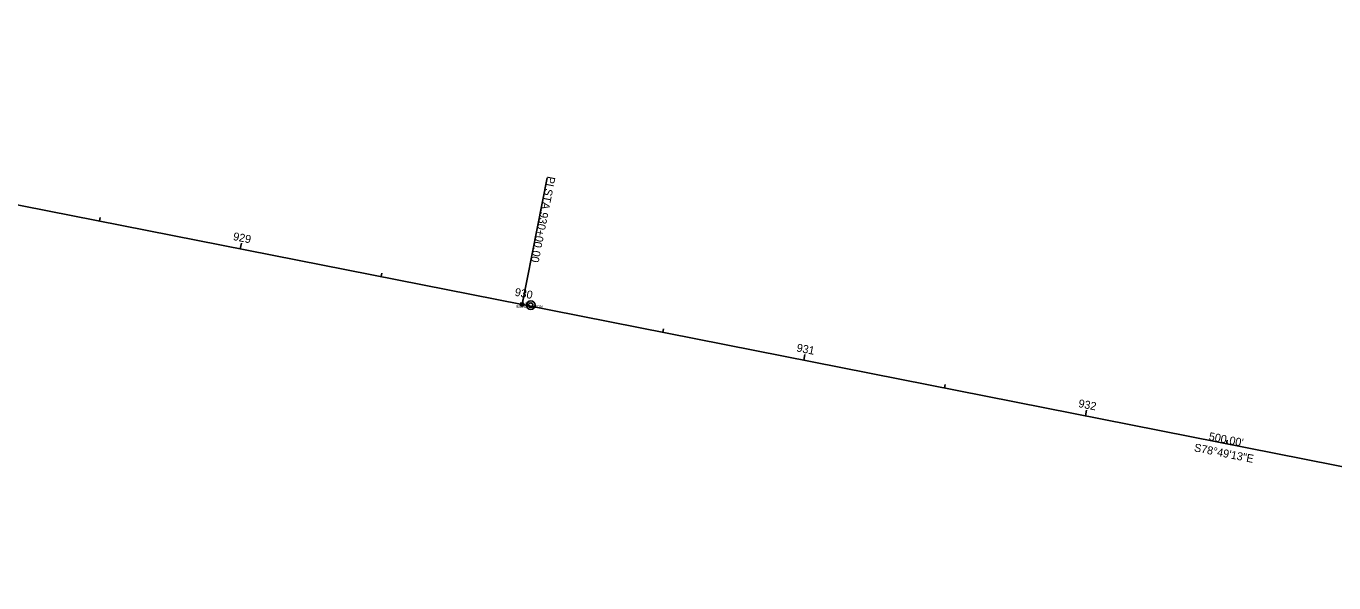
# Model space of a CAD drawing. Extents: x 2061744 to 2069155, y 709240 to 710416.
# Drawn here: x 2064516.3 to 2064971.6, y 709691.4 to 709885.3 of the extents above; entities that cross this region are included whole.
import ezdxf

# ---------------------------------------------------------------- set-up
doc = ezdxf.new("R2010")
doc.units = 0
for name, color, linetype in [('RS_Raster1', 7, 'Continuous'), ('RW_X_CL', 7, 'Continuous'), ('RW_X_CL_100_Bearings', 7, 'Continuous'), ('RW_X_CL_100_Cardinal_Points', 7, 'Continuous'), ('RW_X_CL_100_Distances', 7, 'Continuous'), ('RW_X_CL_100_Stations', 7, 'Continuous'), ('SV_X_Mon_Cells_Found', 7, 'Continuous'), ('SV_X_Text_Comment', 7, 'Continuous'), ('SV_X_Text_Elevation', 7, 'Continuous'), ('SV_X_Text_Name', 7, 'Continuous')]:
    doc.layers.add(name, color=color, linetype=linetype)

msp = doc.modelspace()

# ---------------------------------------------------------------- linework, layer by layer
at = {"layer": 'RS_Raster1'}
for p, q in [((2064198.45, 709885.26), (2064688.97, 709788.32)), ((2064688.97, 709788.32), (2065179.48, 709691.38))]:
    msp.add_line(p, q, dxfattribs=at)
at = {"layer": 'RW_X_CL'}
for p, q in [((2064198.45, 709885.26), (2064688.97, 709788.32)), ((2064688.97, 709788.32), (2065179.48, 709691.38))]:
    msp.add_line(p, q, dxfattribs=at)
at = {"layer": 'RW_X_CL_100_Cardinal_Points'}
msp.add_line((2064688.97, 709788.32), (2064697.69, 709832.47), dxfattribs=at)
msp.add_circle((2064688.97, 709788.32), 0.6, dxfattribs=at)
at = {"layer": 'RW_X_CL_100_Stations'}
for p, q in [((2064541.81, 709817.41), (2064542.05, 709818.58)), ((2064590.86, 709807.71), (2064591.25, 709809.67)), ((2064639.91, 709798.02), (2064640.15, 709799.19)), ((2064688.97, 709788.32), (2064689.35, 709790.28)), ((2064738.02, 709778.63), (2064738.25, 709779.81)), ((2064787.07, 709768.93), (2064787.46, 709770.9)), ((2064836.12, 709759.24), (2064836.35, 709760.42)), ((2064885.17, 709749.55), (2064885.56, 709751.51)), ((2064934.22, 709739.85), (2064934.45, 709741.03))]:
    msp.add_line(p, q, dxfattribs=at)
at = {"layer": 'SV_X_Mon_Cells_Found'}
for radius in [1.5, 0.8]:
    msp.add_circle((2064691.98, 709788.09), radius, dxfattribs=at)

# ---------------------------------------------------------------- texts
at = {"layer": 'RW_X_CL_100_Bearings'}
msp.add_text('S78°49\'13"E', height=2.8, rotation=348.8204, dxfattribs=at).set_placement((2064922.79, 709737.22))
at = {"layer": 'RW_X_CL_100_Cardinal_Points'}
for s, p in [('PI', (2064697.86, 709833.14)), (' STA. ', (2064697.22, 709829.89)), ('930+00.00', (2064695.41, 709820.74))]:
    msp.add_text(s, height=2.8, rotation=258.8204, dxfattribs=at).set_placement(p)
at = {"layer": 'RW_X_CL_100_Distances'}
msp.add_text("500.00'", height=2.8, rotation=348.8204, dxfattribs=at).set_placement((2064927.91, 709741.14))
at = {"layer": 'RW_X_CL_100_Stations'}
for s, p in [('929', (2064588.18, 709810.79)), ('930', (2064686.24, 709791.41)), ('931', (2064784.39, 709772.01)), ('932', (2064882.51, 709752.62))]:
    msp.add_text(s, height=2.8, rotation=348.8204, dxfattribs=at).set_placement(p)
at = {"layer": 'SV_X_Text_Comment'}
msp.add_text('CMON', height=1, dxfattribs=at).set_placement((2064691.98, 709787.09))
at = {"layer": 'SV_X_Text_Elevation'}
msp.add_text('988.862', height=1, dxfattribs=at).set_placement((2064686.9, 709787.09))
at = {"layer": 'SV_X_Text_Name'}
msp.add_text('MN01', height=1, dxfattribs=at).set_placement((2064688.14, 709788.09))

doc.saveas('drawing.dxf')
